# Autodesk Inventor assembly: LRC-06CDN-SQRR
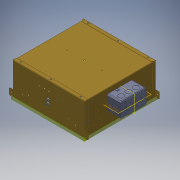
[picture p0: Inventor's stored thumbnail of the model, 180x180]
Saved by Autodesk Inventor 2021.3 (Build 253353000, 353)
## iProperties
Part Number: LRC-06CDN-SQRR
Document SubType Name: Assembly
Designer: JChurch
Author: JChurch
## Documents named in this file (5)
- X:\Revit Files\0000-Un-Zipped\COB\LRC-06CDN-SQR\LRC-06CDN-SQRR.iam
- X:\INVENTOR\830\830376-01-00.iam
- X:\INVENTOR\881\881088-00-00.iam
- X:\INVENTOR\700\700466-00-XX.iam
- X:\INVENTOR\725\725267-00-00.ipt
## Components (4 placed, 4 different names)
1. 830376-01-00:1 [sub-assembly] — Mate:1, Mate:2, Flush:1, Tangent:1, Mate:8
2. 881088-00-00:1 [sub-assembly] — Tangent:1, Mate:3, Mate:4
3. 700466-00-XX:1 [sub-assembly] — Mate:5, Mate:6, Mate:7, Mate:8, Mate:9, Mate:10
4. 725267-00-00:1 — Mate:5, Mate:6, Mate:7
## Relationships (12: Mate 10, Flush 1, Tangent 1)
- Mate:1: 830376-01-00:1
- Mate:2: 830376-01-00:1
- Flush:1: 830376-01-00:1
- Tangent:1: 830376-01-00:1 ↔ 881088-00-00:1
- Mate:3: 881088-00-00:1
- Mate:4: 881088-00-00:1
- Mate:5: 700466-00-XX:1 ↔ 725267-00-00:1
- Mate:6: 700466-00-XX:1 ↔ 725267-00-00:1
- Mate:7: 700466-00-XX:1 ↔ 725267-00-00:1
- Mate:8: 830376-01-00:1 ↔ 700466-00-XX:1
- Mate:9: 700466-00-XX:1
- Mate:10: 700466-00-XX:1
